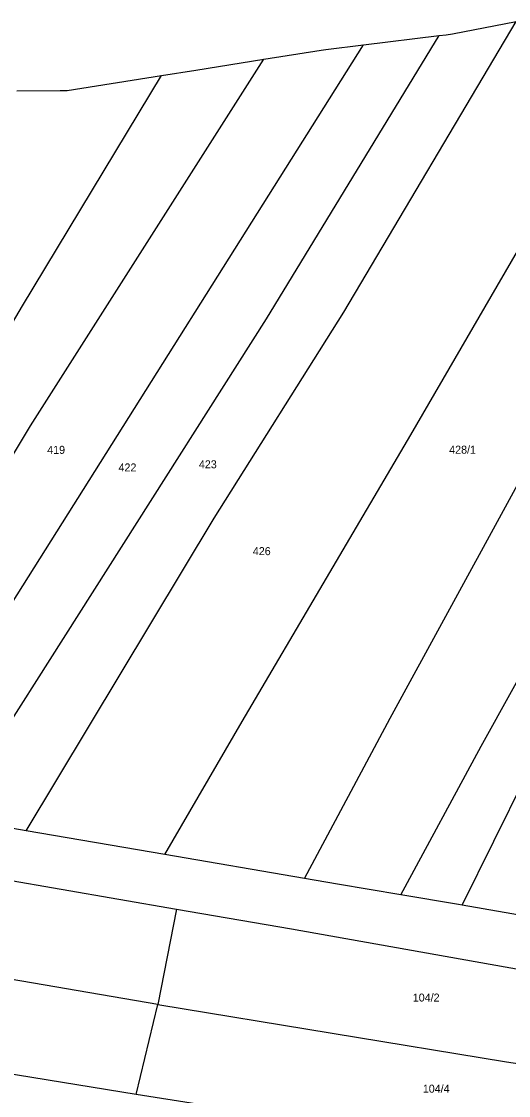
# Model space of a CAD drawing. Extents: x -746176 to -739709, y -1128407 to -1124482.
# Drawn here: x -743344.4 to -743240.9, y -1127120.3 to -1126892.1 of the extents above; entities that cross this region are included whole.
import ezdxf

# ---------------------------------------------------------------- set-up
doc = ezdxf.new("R2010")
doc.units = 0
doc.layers.add('Hranice parcel', color=7, linetype='Continuous')
doc.layers.add('Parcelní čísla', color=7, linetype='Continuous')

msp = doc.modelspace()

# ---------------------------------------------------------------- linework, layer by layer
at = {"layer": 'Hranice parcel'}
for p, q in [((-743271.77, -1126897.03), (-743255.64, -1126895.06)), ((-743271.77, -1126897.03), (-743255.64, -1126895.06)), ((-743343.4, -1127064.01), (-743359.71, -1127061.21)), ((-743313.92, -1127069.06), (-743343.4, -1127064.01)), ((-743284.26, -1127074.14), (-743313.92, -1127069.06)), ((-743206.78, -1127087.5), (-743250.75, -1127079.85)), ((-743311.47, -1127080.65), (-743315.45, -1127100.94)), ((-743320.04, -1127120.06), (-743315.45, -1127100.94))]:
    msp.add_line(p, q, dxfattribs=at)
for points in [[(-743343.4, -1127064.01), (-743303.47, -1126997.62), (-743275.93, -1126953.86), (-743239.29, -1126892.07)], [(-743255.64, -1126895.06), (-743254.17, -1126894.88), (-743252.8, -1126894.71), (-743239.29, -1126892.07)], [(-743255.64, -1126895.06), (-743254.17, -1126894.88), (-743252.8, -1126894.71), (-743239.29, -1126892.07)], [(-743359.71, -1127061.21), (-743292.37, -1126955.23), (-743255.64, -1126895.06)], [(-743373.46, -1127058.85), (-743345.29, -1127013.85), (-743271.77, -1126897.03)], [(-743292.9, -1126900.09), (-743280.74, -1126898.16), (-743279.71, -1126898), (-743271.77, -1126897.03)], [(-743292.9, -1126900.09), (-743280.74, -1126898.16), (-743279.71, -1126898), (-743271.77, -1126897.03)], [(-743389.47, -1127056.13), (-743342.45, -1126977.97), (-743292.9, -1126900.09)], [(-743314.63, -1126903.54), (-743307.33, -1126902.38), (-743292.9, -1126900.09)], [(-743314.63, -1126903.54), (-743307.33, -1126902.38), (-743292.9, -1126900.09)], [(-743313.92, -1127069.06), (-743297.49, -1127040.77), (-743261.68, -1126979.9), (-743236.45, -1126936.5), (-743215.19, -1126899.42)], [(-743401.72, -1127054.05), (-743397.47, -1127044.4), (-743389.37, -1127030.54), (-743365.92, -1126989.29), (-743344.18, -1126952.46), (-743314.63, -1126903.54)], [(-743345.39, -1126906.84), (-743336.16, -1126906.74), (-743334.69, -1126906.72), (-743314.63, -1126903.54)], [(-743345.39, -1126906.84), (-743336.16, -1126906.74), (-743334.69, -1126906.72), (-743314.63, -1126903.54)], [(-743284.26, -1127074.14), (-743266.09, -1127040.1), (-743193, -1126906.14)], [(-743263.8, -1127077.63), (-743246.71, -1127046.03), (-743171.59, -1126910.6)], [(-743250.75, -1127079.85), (-743230.59, -1127039.01), (-743190.96, -1126966.49), (-743161.41, -1126915.91)], [(-743505.37, -1127056.75), (-743500.91, -1127053.2), (-743495.43, -1127050.9), (-743489.52, -1127050.44), (-743483.7, -1127051.01), (-743385.04, -1127067.93), (-743311.47, -1127080.65)], [(-743315.45, -1127100.94), (-743412.49, -1127084.27), (-743458.97, -1127074.63), (-743478.13, -1127070.26), (-743507.61, -1127059.97)], [(-743263.8, -1127077.63), (-743277.29, -1127075.34), (-743284.26, -1127074.14)], [(-743320.04, -1127120.06), (-743373.57, -1127111.3), (-743433.39, -1127101.15), (-743486.65, -1127089.31), (-743518.91, -1127076.75)], [(-743250.75, -1127079.85), (-743251.53, -1127079.71), (-743263.8, -1127077.63)], [(-743311.47, -1127080.65), (-743287.04, -1127084.88), (-743198.26, -1127100.66)], [(-743315.45, -1127100.94), (-743241.34, -1127113.11), (-743196.1, -1127119.89)], [(-743208.12, -1127138.99), (-743257.58, -1127129.9), (-743320.04, -1127120.06)]]:
    msp.add_lwpolyline(points, dxfattribs=at)

# ---------------------------------------------------------------- texts
at = {"layer": 'Parcelní čísla'}
for s, p in [('419', (-743338.93, -1126983.93)), ('428/1', (-743253.54, -1126983.9)), ('422', (-743323.78, -1126987.67)), ('423', (-743306.71, -1126987)), ('426', (-743295.25, -1127005.45)), ('104/2', (-743261.27, -1127100.3)), ('104/4', (-743259.14, -1127119.66))]:
    msp.add_text(s, height=1.7, dxfattribs=at).set_placement(p)

doc.saveas('drawing.dxf')
